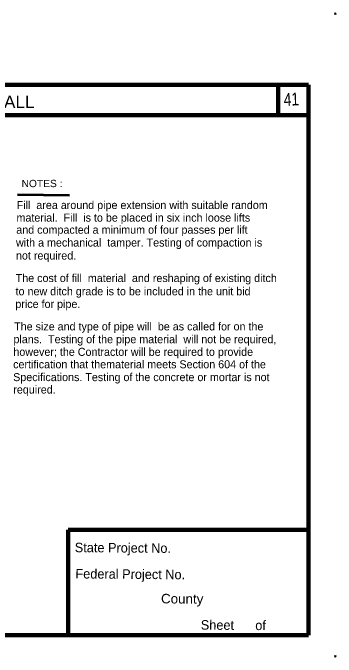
# Model space of a CAD drawing. Extents: x -8731 to 7714, y -62866 to -56618.
# Drawn here: x 7114 to 7714, y -62866 to -61670 of the extents above; entities that cross this region are included whole.
import ezdxf
from ezdxf.enums import TextEntityAlignment as Align

# ---------------------------------------------------------------- set-up
doc = ezdxf.new("R2010")
doc.units = 0
doc.header["$LTSCALE"] = 6
doc.header["$PDMODE"] = 32
doc.header["$PDSIZE"] = 3
doc.layers.add('1', color=7, linetype='Continuous', lineweight=13)
doc.layers.add('3', color=7, linetype='Continuous', lineweight=53)

msp = doc.modelspace()

# ---------------------------------------------------------------- linework, layer by layer
at = {"layer": '1', "lineweight": 100}
for p, q in [((7662.46, -61803.8), (6170.24, -61803.8)), ((7606.22, -61803.8), (7606.22, -61860.06)), ((7662.46, -61803.8), (7662.46, -62825.24)), ((7662.46, -61860.06), (6170.24, -61860.06)), ((7216.74, -62629.56), (7662.46, -62629.56)), ((7216.74, -62629.56), (7216.74, -62825.24)), ((7662.46, -62825.24), (7022.34, -62825.24))]:
    msp.add_line(p, q, dxfattribs=at)
msp.add_lwpolyline([(6170.24, -61807.3), (6170.24, -62825.24), (7661, -62825.24)], dxfattribs=at)
at = {"layer": '1'}
for p in [(7712.4, -61671.6), (7712.4, -62864.2)]:
    msp.add_point(p, dxfattribs=at)
at = {"layer": '3'}
msp.add_line((7122.78, -62007.22), (7219.1, -62008.1), dxfattribs=at)

# ---------------------------------------------------------------- texts
at = {"layer": '1'}
for s, height, rotation, width, p in [('41', 23.78, 2.121, 0.8, (7617.18, -61842.68)), ('County', 17.66, 359.537, 1.05, (7389.02, -62765.92))]:
    msp.add_text(s, height=height, rotation=rotation, dxfattribs=dict(at, width=width)).set_placement(p)
for s, p in [('State Project No.', (7229.02, -62670.92)), ('Federal Project No.', (7230.28, -62719.68)), ('Sheet      of', (7462.78, -62814.68))]:
    msp.add_text(s, height=17.66, rotation=359.537, dxfattribs=at).set_placement(p)
at = {"layer": '3', "width": 1.05}
msp.add_text('PIPE EXTENSION AT HEADWALL ', height=22.7, dxfattribs=at).set_placement((6909.18, -61846.6), align=Align.CENTER)
msp.add_text('NOTES :', height=13.53, dxfattribs=at).set_placement((7130.36, -61993.48))
at = {"layer": '3'}
for s, p in [('Fill  area around pipe extension with suitable random', (7121.34, -62034.12)), ('material.  Fill  is to be placed in six inch loose lifts', (7120.98, -62057.5)), ('and compacted a minimum of four passes per lift', (7120.66, -62079.94)), ('with a mechanical  tamper. Testing of compaction is', (7120.14, -62103.78)), ('not required.', (7120.06, -62127.9)), ('The cost of fill  material  and reshaping of existing ditch', (7119.5, -62169.62)), ('to new ditch grade is to be included in the unit bid', (7119.34, -62194.16)), ('price for pipe.', (7118.92, -62217.76)), ('The size and type of pipe will  be as called for on the ', (7116.64, -62259.4)), ('plans.  Testing of the pipe material  will not be required,', (7115.38, -62283.14)), ('however; the Contractor will be required to provide ', (7115.22, -62306.6)), ('certification that thematerial meets Section 604 of the ', (7114.74, -62329.68)), ('Specifications. Testing of the concrete or mortar is not', (7114.86, -62353.52)), ('required.', (7115.14, -62376.6))]:
    msp.add_text(s, height=14.88, dxfattribs=at).set_placement(p)

doc.saveas('drawing.dxf')
